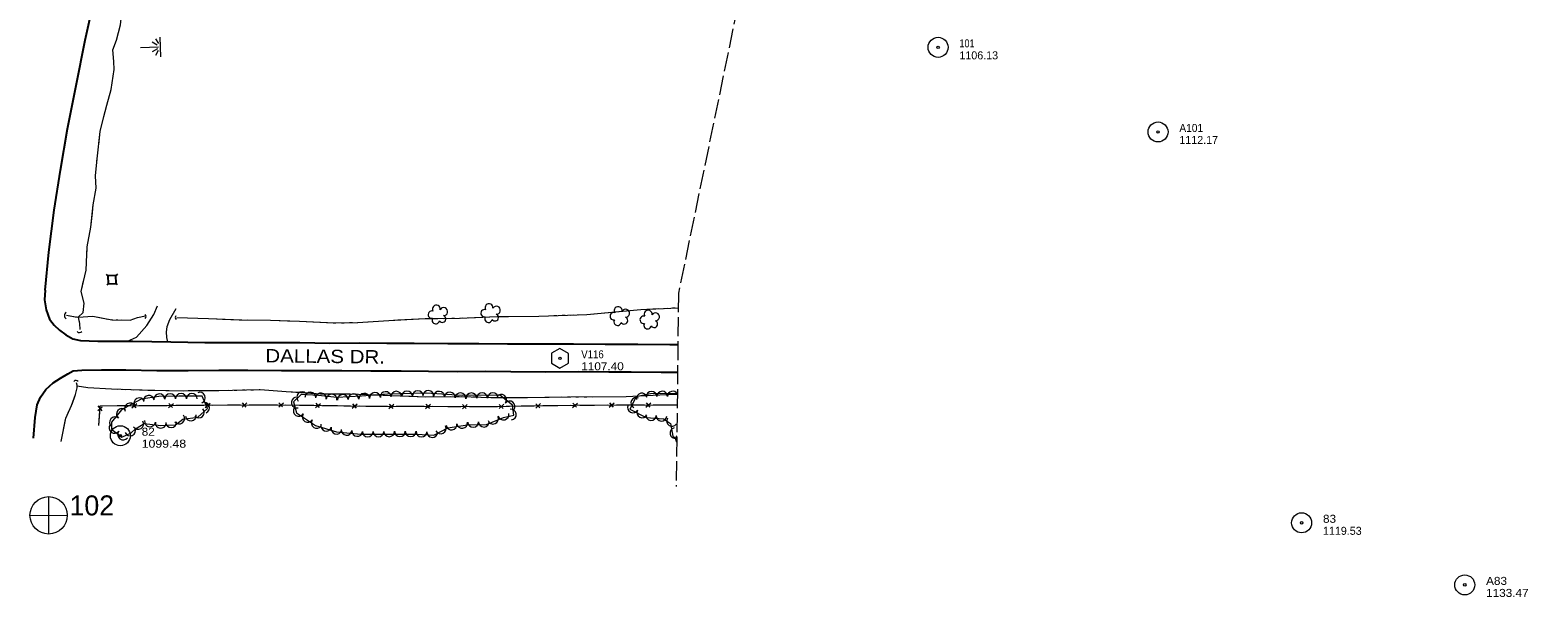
# Model space of a CAD drawing. Extents: x 296527 to 298902, y 45711 to 46924.
# Drawn here: x 297708 to 298831, y 45711 to 46136 of the extents above; entities that cross this region are included whole.
import ezdxf

# ---------------------------------------------------------------- set-up
doc = ezdxf.new("R2010")
doc.units = 0
doc.header["$LTSCALE"] = 2.4
doc.linetypes.add('LONG_DASHED', pattern=[7.5, 6, -1.5])
for name, color, linetype, lineweight in [('11', 7, 'Continuous', 25), ('15', 7, 'Continuous', 13), ('17', 7, 'LONG_DASHED', 13), ('18', 7, 'Continuous', 13), ('19', 7, 'Continuous', 13), ('21', 7, 'Continuous', 25), ('4', 7, 'Continuous', 13), ('5', 7, 'Continuous', 13), ('6', 7, 'Continuous', 13)]:
    doc.layers.add(name, color=color, linetype=linetype, lineweight=lineweight)

msp = doc.modelspace()

# ---------------------------------------------------------------- linework, layer by layer
at = {"layer": '11'}
for points in [[(297719.038, 45940.549), (297721.935, 45969.226), (297725.901, 46000.613), (297730.542, 46030.458), (297735.943, 46061.643), (297742.237, 46093.937), (297749.131, 46127.998), (297756.356, 46161.052)], [(297719.038, 45940.549), (297718.671, 45933.325), (297719.814, 45925.793), (297722.426, 45918.857), (297725.777, 45914.429), (297729.794, 45910.652), (297734.578, 45907.154), (297739.82, 45904.134), (297745.718, 45902.959), (297758.553, 45902.465), (297784.785, 45902.334), (297813.415, 45901.91), (297838.826, 45901.501), (297861.436, 45901.414), (297886.849, 45901.359), (297910.086, 45901.359), (297932.665, 45901.049), (297955.105, 45901.09), (297975.266, 45900.834), (297995.855, 45900.902), (298020.949, 45900.68), (298044.177, 45900.745), (298065.902, 45900.507), (298089.275, 45900.409), (298115.255, 45900.358), (298138.948, 45900.134), (298163.587, 45900.137), (298187.545, 45899.86), (298193.546, 45899.827)], [(297710.461, 45829.675), (297711.517, 45845.159), (297713.091, 45854.817), (297715.508, 45860.439), (297719.666, 45866.266), (297725.091, 45871.212), (297730.717, 45874.763), (297736.086, 45877.925), (297740.116, 45880.201), (297746.645, 45880.812), (297761.423, 45880.94), (297779.511, 45881.015), (297802.762, 45880.388), (297826.453, 45880.45), (297849.272, 45880.694), (297871.11, 45880.721), (297896.329, 45880.453), (297919.605, 45880.53), (297941.615, 45880.515), (297963.293, 45880.295), (297986.084, 45880.086), (298006.61, 45880.026), (298028.485, 45879.781), (298048.996, 45879.945), (298068.24, 45879.649), (298094.286, 45879.483), (298118.721, 45879.604), (298141.643, 45879.532), (298158.496, 45879.364), (298180.92, 45879.288), (298193.302, 45879.291)]]:
    msp.add_lwpolyline(points, dxfattribs=at)
at = {"layer": '15'}
for p, q in [((297758.569, 45850.581), (297761.85, 45853.169)), ((297761.756, 45850.237), (297758.761, 45854.082)), ((297761.898, 45854.041), (297773.088, 45854.107)), ((297773.088, 45854.107), (297782.93, 45854.165)), ((297784.087, 45852.452), (297787.743, 45855.676)), ((297784.236, 45855.655), (297787.019, 45852.537)), ((297789.437, 45854.203), (297800.627, 45854.269)), ((297800.627, 45854.269), (297810.469, 45854.327)), ((297811.626, 45852.615), (297815.281, 45855.838)), ((297811.775, 45855.817), (297814.558, 45852.699)), ((297816.976, 45854.365), (297828.166, 45854.431)), ((297839.166, 45852.782), (297842.82, 45856.007)), ((297839.313, 45855.985), (297842.097, 45852.868)), ((297844.515, 45854.536), (297855.705, 45854.608)), ((297855.705, 45854.608), (297865.547, 45854.672)), ((297866.705, 45852.96), (297870.358, 45856.185)), ((297866.852, 45856.163), (297869.636, 45853.046)), ((297872.053, 45854.714), (297883.244, 45854.786)), ((297883.244, 45854.786), (297893.086, 45854.849)), ((297894.205, 45853.118), (297897.93, 45856.261)), ((297894.424, 45856.317), (297897.138, 45853.138)), ((297899.592, 45854.751), (297910.781, 45854.574)), ((297910.781, 45854.574), (297920.622, 45854.417)), ((297921.741, 45852.68), (297925.466, 45855.823)), ((297921.96, 45855.879), (297924.674, 45852.701)), ((297927.128, 45854.314), (297938.317, 45854.136)), ((297938.317, 45854.136), (297948.158, 45853.98)), ((297949.277, 45852.243), (297953.002, 45855.385)), ((297949.496, 45855.441), (297952.21, 45852.263)), ((297965.854, 45853.775), (297975.696, 45853.739)), ((297976.837, 45852.016), (297980.522, 45855.205)), ((297977.016, 45855.217), (297979.769, 45852.073)), ((297982.202, 45853.716), (297993.393, 45853.676)), ((297993.393, 45853.676), (298003.235, 45853.641)), ((298004.376, 45851.918), (298008.061, 45855.106)), ((298004.555, 45855.119), (298007.308, 45851.974)), ((298009.742, 45853.617), (298020.932, 45853.577)), ((298020.932, 45853.577), (298030.775, 45853.542)), ((298031.915, 45851.819), (298035.601, 45855.007)), ((298032.095, 45855.02), (298034.847, 45851.876)), ((298037.281, 45853.519), (298048.472, 45853.479)), ((298059.488, 45851.894), (298063.108, 45855.157)), ((298059.603, 45855.098), (298062.418, 45852.01)), ((298064.818, 45853.702), (298076.007, 45853.888)), ((298076.007, 45853.888), (298085.849, 45854.052)), ((298087.024, 45852.352), (298090.644, 45855.615)), ((298087.138, 45855.556), (298089.954, 45852.468)), ((298092.354, 45854.16), (298103.543, 45854.346)), ((298103.543, 45854.346), (298113.384, 45854.51)), ((298114.559, 45852.81), (298118.18, 45856.072)), ((298114.674, 45856.014), (298117.49, 45852.926)), ((298119.89, 45854.57), (298131.081, 45854.6)), ((298131.081, 45854.6), (298140.923, 45854.627)), ((298142.075, 45852.911), (298145.74, 45856.123)), ((298142.234, 45856.113), (298145.006, 45852.986)), ((298147.429, 45854.645), (298158.62, 45854.675)), ((298158.62, 45854.675), (298168.463, 45854.702)), ((298169.614, 45852.986), (298173.279, 45856.198)), ((298169.773, 45856.188), (298172.546, 45853.061)), ((298174.969, 45854.72), (298186.159, 45854.75)), ((298186.159, 45854.75), (298193.011, 45854.769)), ((297759.438, 45839.359), (297759.977, 45849.187))]:
    msp.add_line(p, q, dxfattribs=at)
for points in [[(297759.438, 45839.359), (297760.243, 45854.031), (297830.178, 45854.443), (297893.328, 45854.851), (297959.644, 45853.797), (298050.856, 45853.47), (298116.404, 45854.56), (298193.011, 45854.769)], [(297828.166, 45854.431), (297830.178, 45854.443), (297838.008, 45854.494)], [(297954.664, 45853.876), (297959.644, 45853.797), (297965.854, 45853.775)], [(298048.472, 45853.479), (298050.856, 45853.47), (298058.313, 45853.594)]]:
    msp.add_lwpolyline(points, dxfattribs=at)
for centre, radius, start, end in [((297736.68, 45921.554), 3.088, 125.36009, 231.59966), ((297793.052, 45920.881), 1.788, 307.15989, 53.39946), ((297818.248, 45920.105), 1.695, 127.83039, 234.06996), ((297744.785, 45910.934), 2.127, 219.72669, 325.96626), ((297742.204, 45871.005), 2.004, 32.89183, 139.13139)]:
    msp.add_arc(centre, radius, start, end, dxfattribs=at)
at = {"layer": '17'}
for points in [[(297780.83, 45902.354), (297787.559, 45905.55), (297795.264, 45914.226), (297800.644, 45922.371), (297803.417, 45928.802)], [(297817.027, 45926.691), (297812.307, 45918.431), (297810.46, 45913.217), (297809.849, 45909.545), (297810.122, 45905.17), (297810.686, 45903.055), (297811.138, 45901.944)]]:
    msp.add_lwpolyline(points, dxfattribs=at)
at = {"layer": '18'}
for points in [[(297793.445, 45840.753), (297805.824, 45839.169), (297816.854, 45839.725), (297822.388, 45843.869), (297833.615, 45845.37), (297840.728, 45852.059), (297836.892, 45861.238), (297819.377, 45861.306), (297804.243, 45860.938), (297791.207, 45859.016), (297783.984, 45855.17), (297776.411, 45850.922), (297768.746, 45841.701), (297768.736, 45836.595), (297776.7, 45830.507), (297783.719, 45833.633), (297786.956, 45836.804)], [(297997.237, 45832.863), (298010.629, 45832.089), (298021.031, 45837.433), (298035.793, 45839.703), (298049.932, 45840.077), (298062.679, 45845.255), (298070.503, 45847.087), (298069.58, 45854.518), (298060.127, 45861.851), (298031.788, 45861.652), (298005.123, 45863.583), (297975.87, 45862.745), (297956.284, 45861.238), (297937.785, 45860.325), (297924.13, 45861.837), (297910.981, 45862.581), (297905.386, 45857.055), (297907.602, 45848.686), (297921.933, 45839.17), (297937.493, 45834.609), (297955.847, 45832.742), (297961.784, 45832.664)]]:
    msp.add_lwpolyline(points, close=True, dxfattribs=at)
msp.add_lwpolyline([(298193.11, 45863.107), (298172.93, 45862.949), (298162.257, 45860.745), (298157.487, 45851.527), (298169.731, 45845.167), (298182.726, 45844.303), (298187.955, 45840.807), (298189.873, 45831.14), (298192.704, 45828.913)], dxfattribs=at)
for centre, radius, start, end in [((298009.034, 45922.332), 2.777, 72.91576, 280.68875), ((298012.394, 45926.526), 2.974, 349.94487, 211.17875), ((298016.903, 45919.136), 2.611, 212.30092, 70.23353), ((298017.91, 45924.566), 2.975, 267.59569, 150.56896), ((298048.587, 45923.374), 2.777, 72.91576, 280.68875), ((298051.503, 45919.237), 2.783, 149.59278, 350.60382), ((298051.947, 45927.568), 2.974, 349.94487, 211.17875), ((298056.456, 45920.178), 2.611, 212.30092, 70.23353), ((298057.463, 45925.608), 2.975, 267.59569, 150.56896), ((298145.415, 45921.1), 2.777, 72.91576, 280.68875), ((298148.775, 45925.294), 2.974, 349.94487, 211.17875), ((298153.284, 45917.904), 2.611, 212.30092, 70.23353), ((298154.291, 45923.334), 2.975, 267.59569, 150.56896), ((298167.887, 45918.482), 2.777, 72.91576, 280.68875), ((298171.247, 45922.676), 2.974, 349.94487, 211.17875), ((298176.763, 45920.716), 2.975, 267.59569, 150.56896), ((298011.95, 45918.195), 2.783, 149.59278, 350.60382), ((298148.331, 45916.963), 2.783, 149.59278, 350.60382), ((298170.803, 45914.345), 2.783, 149.59278, 350.60382), ((298175.756, 45915.286), 2.611, 212.30092, 70.23353), ((297835.066, 45860.077), 4.074, 292.68822, 112.6729), ((297911.771, 45860.396), 4.03, 44.65217, 224.63685), ((297917.937, 45860.075), 4.03, 356.76919, 176.75387), ((297974.467, 45860.521), 4.03, 4.40749, 184.39216), ((297982.418, 45860.822), 4.03, 1.64854, 181.63322), ((297990.474, 45861.053), 4.03, 1.64854, 181.63322), ((297998.531, 45861.284), 4.03, 1.64854, 181.63322), ((298006.371, 45861.378), 4.03, 355.8657, 175.85038), ((298014.41, 45860.796), 4.03, 355.8657, 175.85038), ((298022.448, 45860.213), 4.03, 355.8657, 175.85038), ((298173.836, 45860.89), 3.947, 0.45741, 180.44209), ((298181.729, 45860.952), 3.947, 0.45741, 180.44209), ((298189.621, 45861.014), 3.947, 27.97198, 180.44209), ((297782.712, 45852.011), 4.074, 29.29748, 209.28216), ((297789.835, 45855.869), 4.074, 28.04143, 208.02611), ((297796.918, 45857.702), 4.074, 8.39481, 188.37948), ((297804.724, 45858.817), 4.074, 1.4006, 181.38528), ((297812.869, 45859.015), 4.074, 1.4006, 181.38528), ((297820.955, 45859.167), 4.074, 359.78522, 179.7699), ((297829.103, 45859.136), 4.074, 359.78522, 179.7699), ((297838.208, 45852.559), 4.074, 292.68822, 112.6729), ((297907.724, 45856.465), 4.03, 104.83847, 284.82315), ((297925.862, 45859.523), 4.03, 353.68912, 173.67379), ((297933.873, 45858.636), 4.03, 353.68912, 173.67379), ((297942.241, 45858.433), 4.03, 2.83315, 182.81782), ((297950.291, 45858.83), 4.03, 2.83315, 182.81782), ((297958.395, 45859.285), 4.03, 4.40749, 184.39216), ((297966.431, 45859.903), 4.03, 4.40749, 184.39216), ((298030.487, 45859.631), 4.03, 355.8657, 175.85038), ((298038.711, 45859.591), 4.03, 0.40999, 180.39467), ((298046.77, 45859.648), 4.03, 0.40999, 180.39467), ((298054.83, 45859.704), 4.03, 0.40999, 180.39467), ((298061.005, 45858.5), 4.03, 322.20576, 142.19044), ((298067.373, 45853.56), 4.03, 322.20576, 142.19044), ((298159.78, 45852.664), 3.947, 152.55858, 332.54326), ((298162.255, 45856.246), 3.947, 62.64764, 242.63232), ((298166.49, 45859.51), 3.947, 11.67537, 191.66005), ((297771.488, 45841.663), 4.074, 50.27245, 230.25713), ((297776.696, 45847.929), 4.074, 50.27245, 230.25713), ((297788.857, 45840.457), 4.074, 211.33103, 31.31571), ((297797.757, 45842.351), 4.074, 172.7158, 352.70047), ((297805.839, 45841.317), 4.074, 172.7158, 352.70047), ((297813.597, 45841.696), 4.074, 182.89338, 2.87806), ((297819.573, 45844.426), 4.074, 216.83446, 36.81914), ((297828.279, 45846.808), 4.074, 187.62269, 7.60737), ((297834.376, 45849.013), 4.074, 223.24808, 43.23276), ((297909.245, 45850.127), 4.03, 146.4229, 326.40758), ((297915.959, 45845.669), 4.03, 146.4229, 326.40758), ((297922.673, 45841.211), 4.03, 146.4229, 326.40758), ((298031.741, 45841.214), 4.03, 188.74974, 8.73442), ((298040.02, 45841.925), 4.03, 181.52288, 1.50756), ((298048.077, 45842.138), 4.03, 181.52288, 1.50756), ((298054.938, 45844.387), 4.03, 202.1153, 22.09998), ((298062.744, 45847.437), 4.03, 193.18613, 13.1708), ((298068.338, 45847.408), 4.03, 277.08807, 97.07275), ((298166.784, 45849.026), 3.947, 152.55858, 332.54326), ((298173.359, 45846.996), 3.947, 176.20383, 356.18851), ((298181.234, 45846.472), 3.947, 176.20383, 356.18851), ((298189.078, 45842.541), 3.947, 146.2418, 326.22648), ((297771.079, 45837.488), 4.074, 142.61192, 322.5966), ((297777.552, 45832.54), 4.074, 142.61192, 322.5966), ((297782.766, 45835.543), 4.074, 204.01406, 23.99874), ((297929.769, 45839.071), 4.03, 163.67057, 343.65524), ((297937.504, 45836.804), 4.03, 163.67057, 343.65524), ((297945.121, 45835.953), 4.03, 174.19942, 354.18409), ((297953.139, 45835.138), 4.03, 174.19942, 354.18409), ((297960.997, 45834.784), 4.03, 179.25496, 359.23963), ((297969.017, 45834.814), 4.03, 180.32926, 0.31394), ((297977.077, 45834.859), 4.03, 180.32926, 0.31394), ((297985.136, 45834.905), 4.03, 180.32926, 0.31394), ((297993.196, 45834.95), 4.03, 180.32926, 0.31394), ((298001.382, 45834.736), 4.03, 176.69989, 356.68457), ((298009.429, 45834.271), 4.03, 176.69989, 356.68457), ((298015.656, 45837.043), 4.03, 207.19937, 27.18405), ((298023.775, 45839.989), 4.03, 188.74974, 8.73442), ((298191.511, 45833.496), 3.947, 101.2298, 281.21448), ((298195.788, 45829.116), 3.947, 141.82011, 217.99575)]:
    msp.add_arc(centre, radius, start, end, dxfattribs=at)
at = {"layer": '19'}
for p, q in [((297770.676, 46122.825), (297771.406, 46124.706)), ((297790.557, 46122.587), (297803.973, 46122.927)), ((297803.167, 46124.337), (297799.262, 46126.439)), ((297801.89, 46129.091), (297804.073, 46125.461)), ((297805.811, 46115.547), (297805.435, 46130.337)), ((297770.188, 46116.931), (297770.026, 46118.943)), ((297803.238, 46121.533), (297799.445, 46119.236)), ((297802.205, 46116.72), (297804.2, 46120.457)), ((297758.558, 46043.621), (297758.786, 46045.627)), ((297757.308, 46031.575), (297757.505, 46033.584)), ((297750.208, 45963.508), (297750.317, 45965.524)), ((297749.882, 45957.461), (297749.991, 45959.477)), ((297748.856, 45951.512), (297749.307, 45953.48)), ((297735.122, 45921.941), (297741.649, 45920.756)), ((297742.554, 45920.625), (297743.006, 45920.563)), ((297743.876, 45920.402), (297743.957, 45919.953)), ((298100.632, 45921.594), (298102.704, 45921.663)), ((298106.847, 45921.801), (298108.918, 45921.87)), ((298113.061, 45922.008), (298115.133, 45922.077)), ((298183.338, 45927.023), (298185.409, 45927.113)), ((298189.551, 45927.293), (298191.622, 45927.382)), ((297744.119, 45919.054), (297744.199, 45918.605)), ((297764.773, 45919.261), (297766.032, 45919.033)), ((297772.378, 45918.427), (297773.658, 45918.407)), ((297852.119, 45918.925), (297854.19, 45918.843)), ((297858.333, 45918.679), (297860.404, 45918.597)), ((297941.184, 45916.231), (297943.256, 45916.276)), ((297947.399, 45916.366), (297949.471, 45916.411)), ((298017.769, 45919.543), (298019.84, 45919.578)), ((298023.984, 45919.648), (298026.055, 45919.683)), ((298030.199, 45919.764), (298032.269, 45919.851)), ((297777.339, 45866.397), (297779.423, 45866.319)), ((297783.59, 45866.163), (297785.674, 45866.085)), ((297860.726, 45865.737), (297862.811, 45865.778)), ((297866.98, 45865.861), (297869.065, 45865.902)), ((297873.234, 45865.984), (297875.319, 45866.026)), ((297737.894, 45852.054), (297738.366, 45853.097)), ((297944.014, 45863.006), (297946.099, 45863)), ((297950.267, 45862.901), (297952.351, 45862.821)), ((297956.518, 45862.662), (297958.602, 45862.582)), ((298027.367, 45860.974), (298029.451, 45860.991)), ((298033.619, 45860.925), (298035.703, 45860.863)), ((298039.869, 45860.738), (298041.953, 45860.675)), ((298110.716, 45860.69), (298112.801, 45860.716)), ((298116.971, 45860.738), (298119.057, 45860.747)), ((298123.227, 45860.764), (298125.313, 45860.773)), ((297731.165, 45827.332), (297734.356, 45843.63)), ((297735.061, 45845.794), (297735.533, 45846.837)), ((297736.477, 45848.924), (297736.95, 45849.967))]:
    msp.add_line(p, q, dxfattribs=at)
for points in [[(297772.796, 46128.492), (297775.522, 46139.511), (297776.952, 46150.575), (297777.136, 46157.325)], [(297743.868, 45920.446), (297747.663, 45924.04), (297748.3, 45930.814), (297746.116, 45939.575), (297749.777, 45955.527), (297750.724, 45973.045), (297753.413, 45987.989), (297755.167, 46004.495), (297757.314, 46017.189), (297756.795, 46026.343), (297758.047, 46039.115), (297760.366, 46059.56), (297763.199, 46070.864), (297765.283, 46079.195), (297768.674, 46090.977), (297770.894, 46106.018), (297770.577, 46112.097), (297769.879, 46120.77), (297772.657, 46127.931), (297775.522, 46139.511)], [(297770.64, 46110.894), (297770.577, 46112.097), (297770.512, 46112.908)], [(297765.05, 46078.264), (297765.283, 46079.195), (297768.674, 46090.977), (297770.894, 46106.018), (297770.85, 46106.862)], [(297759.241, 46049.639), (297760.366, 46059.56), (297763.199, 46070.864), (297765.05, 46078.264)], [(297757.899, 46037.602), (297758.047, 46039.115), (297758.103, 46039.61)], [(297754.532, 45998.521), (297755.167, 46004.495), (297757.314, 46017.189), (297756.795, 46026.343), (297756.914, 46027.557)], [(297750.535, 45969.555), (297750.724, 45973.045), (297753.413, 45987.989), (297754.532, 45998.521)], [(297743.868, 45920.446), (297747.663, 45924.04), (297748.3, 45930.814), (297746.116, 45939.575), (297747.953, 45947.577)], [(297735.122, 45921.941), (297741.829, 45920.723), (297743.868, 45920.446), (297744.745, 45915.575), (297745.066, 45911.129)], [(297743.868, 45920.446), (297754.801, 45921.069), (297769.088, 45918.479), (297782.916, 45918.262), (297788.277, 45920.199), (297794.323, 45921.319)], [(297743.868, 45920.446), (297754.801, 45921.069), (297762.256, 45919.718)], [(297776.217, 45918.367), (297782.916, 45918.262), (297788.277, 45920.199), (297794.323, 45921.319)], [(297817.94, 45920.184), (297841.692, 45919.338), (297865.023, 45918.414), (297888.192, 45918.119), (297909.889, 45917.462), (297935.104, 45916.099), (297953.226, 45916.492), (297976.796, 45918.012), (298004.166, 45919.313), (298029.769, 45919.746), (298058.051, 45920.929), (298089.183, 45921.213), (298125.349, 45922.417), (298165.674, 45926.258), (298193.874, 45927.48)], [(297817.94, 45920.184), (297841.692, 45919.338), (297847.977, 45919.089)], [(298036.411, 45920.024), (298058.051, 45920.929), (298066.443, 45921.006)], [(298066.443, 45921.006), (298089.183, 45921.213), (298096.489, 45921.456)], [(298119.276, 45922.215), (298125.349, 45922.417), (298149.223, 45924.691)], [(298149.223, 45924.691), (298165.674, 45926.258), (298179.195, 45926.844)], [(297744.361, 45917.706), (297744.745, 45915.575), (297745.066, 45911.129)], [(297768.549, 45918.577), (297769.088, 45918.479), (297769.82, 45918.468)], [(297864.546, 45918.433), (297865.023, 45918.414), (297866.618, 45918.394)], [(297870.763, 45918.341), (297888.192, 45918.119), (297900.81, 45917.737)], [(297900.81, 45917.737), (297909.889, 45917.462), (297930.83, 45916.33)], [(297934.969, 45916.106), (297935.104, 45916.099), (297937.041, 45916.141)], [(297953.613, 45916.517), (297976.796, 45918.012), (297983.605, 45918.336)], [(297983.605, 45918.336), (298004.166, 45919.313), (298013.625, 45919.473)], [(297731.165, 45827.332), (297734.566, 45844.7), (297738.877, 45854.226), (297741.966, 45862.591), (297743.107, 45867.39), (297743.035, 45869.453), (297742.592, 45871.113)], [(297739.241, 45855.212), (297741.966, 45862.591), (297743.107, 45867.39), (297743.035, 45869.453), (297742.592, 45871.113)], [(297743.055, 45868.875), (297751.204, 45867.701), (297768.848, 45866.714), (297773.172, 45866.552)], [(297743.055, 45868.875), (297751.204, 45867.701), (297768.848, 45866.714), (297790.528, 45865.904), (297822.938, 45865.337), (297849.366, 45865.512), (297880.232, 45866.123), (297899.775, 45864.814), (297925.682, 45863.057), (297947.794, 45862.995), (297978.677, 45861.816), (298004.449, 45860.794), (298031.028, 45861.003), (298053.211, 45860.337), (298080.858, 45860.313), (298113.361, 45860.723), (298154.852, 45860.896), (298184.906, 45862.449), (298193.105, 45862.75)], [(297789.841, 45865.93), (297790.528, 45865.904), (297791.925, 45865.88)], [(297796.095, 45865.807), (297822.938, 45865.337), (297826.328, 45865.359)], [(297826.328, 45865.359), (297849.366, 45865.512), (297856.557, 45865.654)], [(297879.488, 45866.108), (297880.232, 45866.123), (297899.775, 45864.814), (297909.652, 45864.144)], [(297909.652, 45864.144), (297925.682, 45863.057), (297939.845, 45863.017)], [(297962.769, 45862.423), (297978.677, 45861.816), (297992.977, 45861.249)], [(297992.977, 45861.249), (298004.449, 45860.794), (298023.197, 45860.941)], [(298046.119, 45860.55), (298053.211, 45860.337), (298076.326, 45860.317)], [(298076.326, 45860.317), (298080.858, 45860.313), (298106.548, 45860.637)], [(298129.484, 45860.79), (298154.852, 45860.896), (298159.715, 45861.147)], [(298159.715, 45861.147), (298184.906, 45862.449), (298189.916, 45862.633)]]:
    msp.add_lwpolyline(points, dxfattribs=at)
at = {"layer": '21'}
for p, q in [((297766.199, 45951.42), (297765.112, 45952.453)), ((297766.351, 45945.421), (297765.317, 45944.336)), ((297773.23, 45952.659), (297772.196, 45951.573)), ((297773.436, 45944.541), (297772.348, 45945.574))]:
    msp.add_line(p, q, dxfattribs=at)
msp.add_lwpolyline([(297772.348, 45945.574), (297772.196, 45951.573), (297766.199, 45951.42), (297766.351, 45945.421)], close=True, dxfattribs=at)
at = {"layer": '4'}
for p, q in [((297721.657, 45785.951), (297721.592, 45758.097)), ((297707.748, 45771.921), (297735.653, 45771.908))]:
    msp.add_line(p, q, dxfattribs=at)
at = {"layer": '4', "linetype": 'LONG_DASHED'}
msp.add_lwpolyline([(298394.638, 46912.137), (298194.005, 45938.519), (298192.285, 45793.642)], dxfattribs=at)
at = {"layer": '4'}
msp.add_circle((297721.709, 45771.929), 14, dxfattribs=at)
at = {"layer": '5'}
msp.add_lwpolyline([(298098.648, 45893.364), (298098.648, 45885.973), (298105.108, 45882.246), (298111.505, 45885.911), (298111.505, 45893.24), (298104.983, 45896.966)], close=True, dxfattribs=at)
msp.add_circle((298105.062, 45889.601), 0.871, dxfattribs=at)
at = {"layer": '6'}
for centre, radius in [((298388.632, 46122.627), 7.5), ((298388.632, 46122.627), 0.96), ((298553.561, 46059.205), 7.5), ((298553.561, 46059.205), 0.96), ((297775.477, 45831.585), 7.5), ((297775.477, 45831.585), 0.96), ((298661.245, 45766.33), 7.5), ((298661.245, 45766.33), 0.96), ((298783.541, 45719.792), 7.5), ((298783.541, 45719.792), 0.96)]:
    msp.add_circle(centre, radius, dxfattribs=at)

# ---------------------------------------------------------------- texts
at = {"layer": '11', "width": 1.15}
msp.add_text('DALLAS DR.', height=10, rotation=359.391, dxfattribs=at).set_placement((297884.15, 45886.583))
at = {"layer": '4'}
msp.add_text('102', height=15, dxfattribs=at).set_placement((297737.361, 45771.859))
at = {"layer": '5'}
for s, width, p in [('V116', 0.9, (298121.062, 45889.601)), ('1107.40', 1.1, (298121.062, 45880.601))]:
    msp.add_text(s, height=6, dxfattribs=dict(at, width=width)).set_placement(p)
at = {"layer": '6'}
for s, width, p in [('101', 0.85, (298404.632, 46122.627)), ('A101', 0.95, (298569.561, 46059.205)), ('82', 1.1, (297791.477, 45831.585)), ('1099.48', 1.15, (297791.477, 45822.585)), ('83', 1.1, (298677.245, 45766.33)), ('A83', 1.1, (298799.541, 45719.792)), ('1133.47', 1.1, (298799.541, 45710.792))]:
    msp.add_text(s, height=6, dxfattribs=dict(at, width=width)).set_placement(p)
for s, p in [('1106.13', (298404.632, 46113.627)), ('1112.17', (298569.561, 46050.205)), ('1119.53', (298677.245, 45757.33))]:
    msp.add_text(s, height=6, dxfattribs=at).set_placement(p)

doc.saveas('drawing.dxf')
